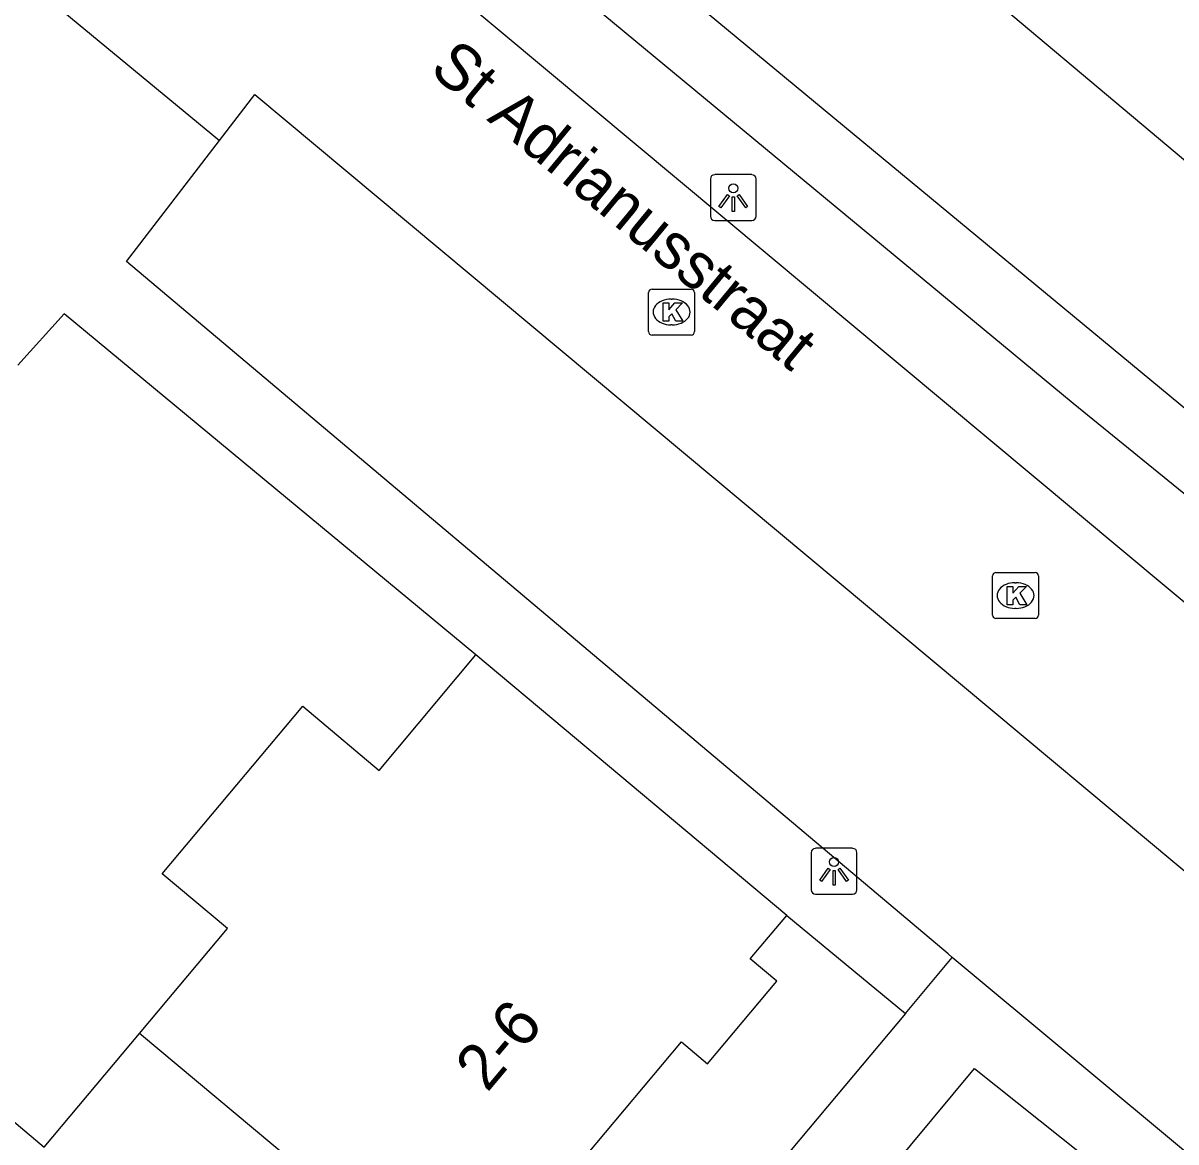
# Model space of a CAD drawing. Extents: x 162074 to 163034, y 381824 to 382557.
# Drawn here: x 162488.23 to 162513.3, y 382096.24 to 382120.58 of the extents above; entities that cross this region are included whole.
import ezdxf

# ---------------------------------------------------------------- set-up
doc = ezdxf.new("R2010")
doc.units = 0
for name, color, linetype in [('IMGEO_Kolk', 7, 'Continuous'), ('IMGEO_Lichtpunt', 7, 'Continuous'), ('IMGEO_Muur', 7, 'Continuous'), ('IMGEO_Openbare_ruimte_label', 7, 'Continuous'), ('IMGEO_Pand', 7, 'Continuous'), ('IMGEO_Pand_nummerreeks', 7, 'Continuous'), ('IMGEO_Rijbaan_lokaal_open', 7, 'Continuous'), ('IMGEO_Voetpad_open', 7, 'Continuous')]:
    doc.layers.add(name, color=color, linetype=linetype)

msp = doc.modelspace()

# ---------------------------------------------------------------- linework, layer by layer
at = {"layer": 'IMGEO_Kolk'}
for p, q in [((162501.833, 382113.869), (162501.833, 382114.721)), ((162501.908, 382114.795), (162502.76, 382114.795)), ((162502.834, 382114.721), (162502.834, 382113.869)), ((162502.321, 382114.575), (162502.346, 382114.575)), ((162502.344, 382114.015), (162502.319, 382114.015)), ((162502.76, 382113.795), (162501.908, 382113.795)), ((162509.39, 382108.628), (162510.242, 382108.628)), ((162509.315, 382107.702), (162509.315, 382108.554)), ((162509.803, 382108.408), (162509.828, 382108.408)), ((162510.316, 382108.554), (162510.316, 382107.702)), ((162510.242, 382107.628), (162509.39, 382107.628)), ((162509.826, 382107.848), (162509.801, 382107.848))]:
    msp.add_line(p, q, dxfattribs=at)
for points in [[(162501.833, 382113.869), (162501.833, 382114.721)], [(162501.908, 382114.795), (162502.76, 382114.795)], [(162502.834, 382114.721), (162502.834, 382113.869)], [(162502.154, 382114.495), (162502.277, 382114.495), (162502.277, 382114.344), (162502.407, 382114.495), (162502.571, 382114.495), (162502.425, 382114.344), (162502.578, 382114.095), (162502.426, 382114.095), (162502.341, 382114.259), (162502.277, 382114.192), (162502.277, 382114.095), (162502.154, 382114.095), (162502.154, 382114.495)], [(162502.76, 382113.795), (162501.908, 382113.795)], [(162509.39, 382108.628), (162510.242, 382108.628)], [(162509.315, 382107.702), (162509.315, 382108.554)], [(162510.316, 382108.554), (162510.316, 382107.702)], [(162509.636, 382108.328), (162509.759, 382108.328), (162509.759, 382108.177), (162509.889, 382108.328), (162510.053, 382108.328), (162509.907, 382108.177), (162510.06, 382107.928), (162509.908, 382107.928), (162509.823, 382108.092), (162509.759, 382108.025), (162509.759, 382107.928), (162509.636, 382107.928), (162509.636, 382108.328)], [(162510.242, 382107.628), (162509.39, 382107.628)]]:
    msp.add_lwpolyline(points, dxfattribs=at)
for centre, start, end in [((162501.91, 382114.719), 91.552, 178.448), ((162501.91, 382114.719), 91.552, 178.448), ((162502.758, 382114.719), 1.552, 88.448), ((162502.758, 382114.719), 1.552, 88.448), ((162501.91, 382113.871), 181.552, 268.448), ((162501.91, 382113.871), 181.552, 268.448), ((162502.758, 382113.871), 271.552, 358.448), ((162502.758, 382113.871), 271.552, 358.448), ((162509.392, 382108.552), 91.552, 178.448), ((162509.392, 382108.552), 91.552, 178.448), ((162510.24, 382108.552), 1.552, 88.448), ((162510.24, 382108.552), 1.552, 88.448), ((162509.392, 382107.704), 181.552, 268.448), ((162509.392, 382107.704), 181.552, 268.448), ((162510.24, 382107.704), 271.552, 358.448), ((162510.24, 382107.704), 271.552, 358.448)]:
    msp.add_arc(centre, 0.0765, start, end, dxfattribs=at)
for centre, major_axis, ratio, start_param, end_param in [((162502.32, 382114.295), (-0.387, 0.002), 0.722429, 4.712389, 7.853982), ((162502.345, 382114.295), (-0.39, 0.002), 0.717154, 1.570796, 4.712389), ((162509.802, 382108.128), (-0.387, 0.002), 0.722429, 4.712389, 7.853982), ((162509.827, 382108.128), (-0.39, 0.002), 0.717154, 1.570796, 4.712389)]:
    msp.add_ellipse(centre, major_axis=major_axis, ratio=ratio, start_param=start_param, end_param=end_param, dxfattribs=at)
at = {"layer": 'IMGEO_Lichtpunt'}
for p, q in [((162503.177, 382117.189), (162503.177, 382116.382)), ((162503.177, 382117.189), (162503.177, 382116.382)), ((162504.079, 382117.284), (162503.271, 382117.284)), ((162504.079, 382117.284), (162503.271, 382117.284)), ((162504.173, 382116.382), (162504.173, 382117.189)), ((162504.173, 382116.382), (162504.173, 382117.189)), ((162503.271, 382116.288), (162504.079, 382116.288)), ((162503.271, 382116.288), (162504.079, 382116.288)), ((162506.271, 382102.629), (162505.463, 382102.629)), ((162506.271, 382102.629), (162505.463, 382102.629)), ((162505.369, 382102.534), (162505.369, 382101.727)), ((162505.369, 382102.534), (162505.369, 382101.727)), ((162506.365, 382101.727), (162506.365, 382102.534)), ((162506.365, 382101.727), (162506.365, 382102.534)), ((162505.463, 382101.633), (162506.271, 382101.633)), ((162505.463, 382101.633), (162506.271, 382101.633))]:
    msp.add_line(p, q, dxfattribs=at)
for points in [[(162503.551, 382116.853), (162503.59, 382116.825), (162503.402, 382116.563), (162503.364, 382116.59), (162503.551, 382116.853)], [(162503.653, 382116.805), (162503.7, 382116.805), (162503.7, 382116.483), (162503.653, 382116.483), (162503.653, 382116.805)], [(162503.763, 382116.825), (162503.801, 382116.852), (162503.988, 382116.59), (162503.949, 382116.562), (162503.763, 382116.825)], [(162505.743, 382102.198), (162505.782, 382102.17), (162505.594, 382101.908), (162505.556, 382101.935), (162505.743, 382102.198)], [(162505.845, 382102.15), (162505.892, 382102.15), (162505.892, 382101.828), (162505.845, 382101.828), (162505.845, 382102.15)], [(162505.955, 382102.17), (162505.993, 382102.197), (162506.18, 382101.935), (162506.141, 382101.907), (162505.955, 382102.17)]]:
    msp.add_lwpolyline(points, dxfattribs=at)
for centre in [(162503.676, 382116.987), (162505.868, 382102.332)]:
    msp.add_circle(centre, 0.0994, dxfattribs=at)
for centre, start, end in [((162503.271, 382117.189), 90, 180), ((162503.271, 382117.189), 90, 180), ((162504.079, 382117.189), 0, 90), ((162504.079, 382117.189), 0, 90), ((162503.271, 382116.382), 180, 270), ((162503.271, 382116.382), 180, 270), ((162504.079, 382116.382), 270, 0), ((162504.079, 382116.382), 270, 360), ((162505.463, 382102.534), 90, 180), ((162505.463, 382102.534), 90, 180), ((162506.271, 382102.534), 0, 90), ((162506.271, 382102.534), 0, 90), ((162505.463, 382101.727), 180, 270), ((162505.463, 382101.727), 180, 270), ((162506.271, 382101.727), 270, 0), ((162506.271, 382101.727), 270, 360)]:
    msp.add_arc(centre, 0.0946, start, end, dxfattribs=at)
at = {"layer": 'IMGEO_Muur'}
msp.add_lwpolyline([(162498.079, 382106.838), (162489.12, 382114.253)], dxfattribs=at)
at = {"layer": 'IMGEO_Pand'}
for points in [[(162514.417, 382116.817), (162505.998, 382123.89)], [(162490.761, 382098.6), (162492.673, 382100.882), (162491.252, 382102.073), (162494.31, 382105.72), (162495.972, 382104.325), (162498.079, 382106.838)], [(162504.837, 382101.171), (162500, 382105.227), (162498.079, 382106.838)], [(162497.798, 382092.71), (162498.587, 382093.651), (162499.124, 382093.201), (162500, 382094.245), (162500.628, 382094.994), (162500.07, 382095.462), (162502.548, 382098.417), (162503.115, 382097.942), (162504.623, 382099.74), (162504.044, 382100.225), (162504.837, 382101.171)], [(162483.743, 382090.108), (162485.653, 382092.386), (162484.368, 382093.463), (162487.463, 382097.156), (162488.689, 382096.129), (162490.761, 382098.6)], [(162497.798, 382092.71), (162490.761, 382098.6)]]:
    msp.add_lwpolyline(points, dxfattribs=at)
at = {"layer": 'IMGEO_Rijbaan_lokaal_open'}
for points in [[(162522.733, 382100.263), (162494.772, 382123.612), (162494.169, 382124.137)], [(162488.342, 382121.462), (162492.498, 382118.029)], [(162492.498, 382118.029), (162493.266, 382119.03), (162517.984, 382098.381)]]:
    msp.add_lwpolyline(points, dxfattribs=at)
at = {"layer": 'IMGEO_Voetpad_open'}
for points in [[(162496.281, 382126.462), (162500, 382123.383), (162526.357, 382101.557)], [(162495.392, 382125.305), (162495.888, 382124.894), (162500, 382121.487), (162511.072, 382112.312), (162522.289, 382103.18), (162523.924, 382101.747), (162522.733, 382100.263)], [(162508.44, 382100.255), (162508.346, 382100.334), (162490.476, 382115.395), (162492.498, 382118.029)], [(162498.079, 382106.838), (162489.12, 382114.253), (162488.112, 382113.139)], [(162504.837, 382101.171), (162507.419, 382099.039)], [(162507.419, 382099.039), (162508.44, 382100.255)], [(162513.64, 382095.914), (162508.44, 382100.255)], [(162507.419, 382099.039), (162500, 382090.184), (162471.924, 382056.673)], [(162498.931, 382085.813), (162500, 382087.1), (162508.922, 382097.842), (162511.276, 382095.959)]]:
    msp.add_lwpolyline(points, dxfattribs=at)

# ---------------------------------------------------------------- texts
at = {"layer": 'IMGEO_Openbare_ruimte_label'}
msp.add_text('St Adrianusstraat', height=1, rotation=320.4365, dxfattribs=at).set_placement((162497.037, 382119.52))
at = {"layer": 'IMGEO_Pand_nummerreeks'}
msp.add_text('2-6', height=1, rotation=50.0175, dxfattribs=at).set_placement((162498.323, 382097.3))

doc.saveas('drawing.dxf')
